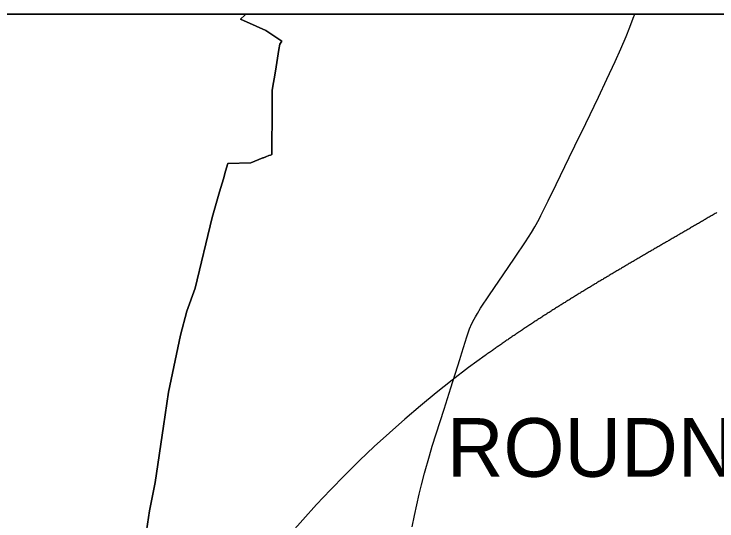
# Model space of a CAD drawing. Extents: x -759276 to -751881, y -1176141 to -1171097.
# Drawn here: x -757130 to -755760, y -1172085 to -1171097 of the extents above; entities that cross this region are included whole.
import ezdxf

# ---------------------------------------------------------------- set-up
doc = ezdxf.new("R2010")
doc.units = 0
for name, color, linetype in [('A_HRU', 7, 'Continuous'), ('A_OBCE', 7, 'Continuous'), ('A_SILNICE', 7, 'Continuous'), ('AA_vyrezy', 7, 'Continuous')]:
    doc.layers.add(name, color=color, linetype=linetype)

msp = doc.modelspace()

# ---------------------------------------------------------------- linework, layer by layer
at = {"layer": 'A_HRU'}
for points in [[(-759275.6, -1176140.6), (-759275.6, -1171097.2), (-751880.9, -1171097.2), (-751880.9, -1176140.6)], [(-751880.9, -1172828.3), (-753894.3, -1172828.3), (-753894.3, -1171097.2), (-759275.6, -1171097.2), (-759275.6, -1176140.6), (-753894.3, -1176140.6), (-753894.3, -1174884.8), (-751880.9, -1174884.8)]]:
    msp.add_lwpolyline(points, close=True, dxfattribs=at)
at = {"layer": 'A_OBCE'}
for p, q in [((-756678.2, -1171097.2), (-757961.8, -1171097.2)), ((-756678.2, -1171097.2), (-756680, -1171099)), ((-755191.2, -1171097.2), (-756678.2, -1171097.2)), ((-756680, -1171099), (-756688.5, -1171107.2)), ((-756657.8, -1171121), (-756688.5, -1171107.2)), ((-756688.5, -1171107.2), (-756657.8, -1171121)), ((-756639.3, -1171129.4), (-756657.8, -1171121)), ((-756657.8, -1171121), (-756639.3, -1171129.4)), ((-756639.3, -1171129.4), (-756607.8, -1171150.2)), ((-756613.8, -1171166.5), (-756619.2, -1171199.9)), ((-756619.2, -1171199.9), (-756622, -1171216.4)), ((-756622, -1171216.4), (-756624.3, -1171230.8)), ((-756624.3, -1171230.8), (-756626.7, -1171245.2)), ((-756626.7, -1171245.2), (-756626.9, -1171278.9)), ((-756633.1, -1171373), (-756630.4, -1171371.9)), ((-756645, -1171377.6), (-756668.7, -1171387)), ((-756643.7, -1171377.1), (-756639.1, -1171375.3)), ((-756639.1, -1171375.3), (-756633.1, -1171373)), ((-756668.7, -1171387), (-756713.4, -1171388.1)), ((-756721.9, -1171418.1), (-756717.7, -1171403.4)), ((-756729.6, -1171443.3), (-756721.9, -1171418.1)), ((-756721.9, -1171418.1), (-756729.6, -1171443.3)), ((-756743.9, -1171493.7), (-756729.6, -1171443.3)), ((-756776.8, -1171631), (-756743.9, -1171493.7)), ((-756828.9, -1171834), (-756805.4, -1171722.9)), ((-756805.4, -1171722.9), (-756828.9, -1171834)), ((-756828.9, -1171834), (-756839, -1171900.1))]:
    msp.add_line(p, q, dxfattribs=at)
for points in [[(-756688.5, -1171107.2), (-756680, -1171099), (-756678.2, -1171097.2)], [(-756613.8, -1171166.5), (-756611.9, -1171155.5), (-756607.8, -1171150.2), (-756639.3, -1171129.4)], [(-756607.8, -1171150.2), (-756611.9, -1171155.5), (-756613.8, -1171166.5)], [(-756626.7, -1171245.2), (-756624.3, -1171230.8), (-756622, -1171216.4), (-756619.2, -1171199.9), (-756613.8, -1171166.5)], [(-756630.4, -1171371.9), (-756627.6, -1171370.8), (-756626.9, -1171278.9), (-756626.7, -1171245.2)], [(-756626.9, -1171278.9), (-756627.6, -1171370.8), (-756630.4, -1171371.9)], [(-756630.4, -1171371.9), (-756633.1, -1171373), (-756639.1, -1171375.3)], [(-756668.7, -1171387), (-756645, -1171377.6), (-756643.7, -1171377.1)], [(-756639.1, -1171375.3), (-756643.7, -1171377.1), (-756645, -1171377.6)], [(-756713.4, -1171388.1), (-756717.7, -1171403.4), (-756721.9, -1171418.1)], [(-756717.7, -1171403.4), (-756713.4, -1171388.1), (-756668.7, -1171387)], [(-756729.6, -1171443.3), (-756743.9, -1171493.7), (-756776.8, -1171631), (-756793.1, -1171676.4), (-756805.4, -1171722.9)], [(-756805.4, -1171722.9), (-756793.1, -1171676.4), (-756776.8, -1171631)], [(-756854.8, -1172009.9), (-756839, -1171900.1), (-756828.9, -1171834)], [(-756839, -1171900.1), (-756854.8, -1172009.9), (-756866.1, -1172065.3)], [(-756881.7, -1172243.8), (-756879.6, -1172156.4), (-756866.1, -1172065.3), (-756854.8, -1172009.9)], [(-756866.1, -1172065.3), (-756879.6, -1172156.4), (-756881.7, -1172243.8)]]:
    msp.add_lwpolyline(points, dxfattribs=at)
at = {"layer": 'A_SILNICE'}
for points in [[(-756353.9, -1172096.2), (-756349.2, -1172074.4), (-756340.1, -1172033), (-756335.9, -1172014.3), (-756330.1, -1171991.7), (-756320.5, -1171958.1), (-756315, -1171939.5), (-756291.9, -1171867.4), (-756278.6, -1171825.2), (-756261.2, -1171770.2), (-756257.2, -1171757.6), (-756247.4, -1171726.4), (-756241.9, -1171710.6), (-756237.4, -1171700.2), (-756233.2, -1171691.6), (-756230.6, -1171686.9), (-756226.9, -1171680.4), (-756220.6, -1171670.2), (-756203.3, -1171644.4), (-756166.8, -1171591.2), (-756153.1, -1171570.9), (-756133.2, -1171540.9), (-756121.6, -1171522.5), (-756114.8, -1171511.6), (-756106.5, -1171496.7), (-756103, -1171490), (-756088.6, -1171461.2), (-756073.1, -1171429.1), (-756047.8, -1171376.9), (-756036.7, -1171354.2), (-756015.5, -1171310.4), (-755990.8, -1171258.9), (-755974.2, -1171223.9), (-755958.4, -1171189.6), (-755947.1, -1171164.8), (-755937.1, -1171141.1), (-755929.7, -1171122.6), (-755923, -1171105.3), (-755920.1, -1171097.2)], [(-755759.8, -1171483.9), (-755761.7, -1171485), (-755763.6, -1171486.1), (-755765.5, -1171487.2), (-755767.4, -1171488.3), (-755769.3, -1171489.4), (-755771.2, -1171490.6), (-755773.1, -1171491.7), (-755775, -1171492.8), (-755776.9, -1171493.9), (-755778.8, -1171495), (-755780.7, -1171496.1), (-755782.6, -1171497.2), (-755784.5, -1171498.3), (-755786.4, -1171499.4), (-755788.3, -1171500.5), (-755790.2, -1171501.6), (-755792.1, -1171502.8), (-755794, -1171503.9), (-755795.9, -1171505), (-755797.8, -1171506.1), (-755799.7, -1171507.2), (-755801.6, -1171508.3), (-755803.5, -1171509.4), (-755805.4, -1171510.5), (-755807.3, -1171511.6), (-755809.2, -1171512.7), (-755811.1, -1171513.8), (-755813, -1171514.9), (-755814.9, -1171516), (-755816.8, -1171517.1), (-755818.7, -1171518.2), (-755820.6, -1171519.4), (-755822.5, -1171520.5), (-755824.4, -1171521.6), (-755826.3, -1171522.7), (-755828.2, -1171523.8), (-755830.1, -1171524.9), (-755832, -1171526), (-755833.9, -1171527.1), (-755835.8, -1171528.2), (-755837.7, -1171529.3), (-755839.6, -1171530.4), (-755841.5, -1171531.5), (-755843.4, -1171532.6), (-755845.3, -1171533.7), (-755847.2, -1171534.8), (-755849.1, -1171535.9), (-755850.9, -1171537), (-755852.8, -1171538.1), (-755854.7, -1171539.1), (-755856.5, -1171540.2), (-755858.4, -1171541.3), (-755860.2, -1171542.4), (-755862.1, -1171543.5), (-755864, -1171544.5), (-755865.8, -1171545.6), (-755867.7, -1171546.7), (-755869.5, -1171547.8), (-755871.4, -1171548.9), (-755873.3, -1171549.9), (-755875.1, -1171551), (-755877, -1171552.1), (-755878.8, -1171553.2), (-755880.7, -1171554.3), (-755882.6, -1171555.3), (-755884.4, -1171556.4), (-755886.3, -1171557.5), (-755888.1, -1171558.6), (-755890, -1171559.7), (-755891.8, -1171560.7), (-755893.7, -1171561.8), (-755895.6, -1171562.9), (-755897.4, -1171564), (-755899.3, -1171565.1), (-755901.1, -1171566.2), (-755903, -1171567.2), (-755904.8, -1171568.3), (-755906.7, -1171569.4), (-755908.6, -1171570.5), (-755910.4, -1171571.6), (-755912.3, -1171572.7), (-755914.1, -1171573.7), (-755916, -1171574.8), (-755917.8, -1171575.9), (-755919.7, -1171577), (-755921.5, -1171578.1), (-755923.4, -1171579.2), (-755925.3, -1171580.3), (-755927.1, -1171581.4), (-755929, -1171582.4), (-755930.8, -1171583.5), (-755932.7, -1171584.6), (-755934.5, -1171585.7), (-755936.4, -1171586.8), (-755938.2, -1171587.9), (-755940.1, -1171589), (-755941.9, -1171590.1), (-755943.8, -1171591.2), (-755945.6, -1171592.3), (-755947.5, -1171593.3), (-755949.3, -1171594.4), (-755951.2, -1171595.5), (-755953, -1171596.6), (-755954.9, -1171597.7), (-755956.7, -1171598.8), (-755958.6, -1171599.9), (-755960.4, -1171601), (-755962.3, -1171602.1), (-755964.1, -1171603.2), (-755966, -1171604.3), (-755967.8, -1171605.4), (-755969.7, -1171606.5), (-755971.5, -1171607.6), (-755973.4, -1171608.7), (-755975.2, -1171609.8), (-755977.1, -1171610.9), (-755978.9, -1171612), (-755980.8, -1171613.1), (-755982.6, -1171614.2), (-755984.5, -1171615.3), (-755986.3, -1171616.4), (-755988.2, -1171617.5), (-755990, -1171618.6), (-755991.8, -1171619.7), (-755993.7, -1171620.8), (-755995.5, -1171621.9), (-755997.4, -1171623.1), (-755999.2, -1171624.2), (-756001, -1171625.3), (-756002.9, -1171626.4), (-756004.7, -1171627.5), (-756006.6, -1171628.6), (-756008.4, -1171629.7), (-756010.2, -1171630.8), (-756012.1, -1171632), (-756013.9, -1171633.1), (-756015.8, -1171634.2), (-756017.6, -1171635.3), (-756019.4, -1171636.4), (-756021.3, -1171637.5), (-756023.1, -1171638.7), (-756024.9, -1171639.8), (-756026.8, -1171640.9), (-756028.6, -1171642), (-756030.4, -1171643.1), (-756032.3, -1171644.3), (-756034.1, -1171645.4), (-756035.9, -1171646.5), (-756037.8, -1171647.6), (-756039.6, -1171648.8), (-756041.4, -1171649.9), (-756043.3, -1171651), (-756045.1, -1171652.2), (-756046.9, -1171653.3), (-756048.7, -1171654.4), (-756050.6, -1171655.6), (-756052.4, -1171656.7), (-756054.2, -1171657.8), (-756056, -1171659), (-756057.9, -1171660.1), (-756059.7, -1171661.2), (-756061.5, -1171662.4), (-756063.3, -1171663.5), (-756065.2, -1171664.7), (-756067, -1171665.8), (-756068.8, -1171667), (-756070.6, -1171668.1), (-756072.4, -1171669.2), (-756074.3, -1171670.4), (-756076.1, -1171671.5), (-756077.9, -1171672.7), (-756079.7, -1171673.8), (-756081.5, -1171675), (-756083.3, -1171676.1), (-756085.2, -1171677.3), (-756087, -1171678.5), (-756088.8, -1171679.6), (-756090.6, -1171680.8), (-756092.4, -1171681.9), (-756094.2, -1171683.1), (-756096, -1171684.2), (-756097.8, -1171685.4), (-756099.6, -1171686.6), (-756101.5, -1171687.7), (-756103.3, -1171688.9), (-756105.1, -1171690.1), (-756106.9, -1171691.2), (-756108.7, -1171692.4), (-756110.5, -1171693.6), (-756112.3, -1171694.7), (-756114.1, -1171695.9), (-756115.9, -1171697.1), (-756117.7, -1171698.3), (-756119.5, -1171699.4), (-756121.3, -1171700.6), (-756123.1, -1171701.8), (-756124.9, -1171703), (-756126.7, -1171704.2), (-756128.5, -1171705.3), (-756130.3, -1171706.5), (-756132.1, -1171707.7), (-756133.9, -1171708.9), (-756135.6, -1171710.1), (-756137.4, -1171711.3), (-756139.2, -1171712.5), (-756141, -1171713.7), (-756142.8, -1171714.9), (-756144.6, -1171716.1), (-756146.4, -1171717.3), (-756148.2, -1171718.5), (-756149.9, -1171719.7), (-756151.7, -1171720.9), (-756153.5, -1171722.1), (-756155.3, -1171723.3), (-756157.1, -1171724.5), (-756158.8, -1171725.7), (-756160.6, -1171726.9), (-756162.4, -1171728.1), (-756164.2, -1171729.3), (-756166, -1171730.5), (-756167.7, -1171731.7), (-756169.5, -1171732.9), (-756171.3, -1171734.2), (-756173, -1171735.4), (-756174.8, -1171736.6), (-756176.6, -1171737.8), (-756178.3, -1171739.1), (-756180.1, -1171740.3), (-756181.9, -1171741.5), (-756183.6, -1171742.7), (-756185.4, -1171744), (-756187.2, -1171745.2), (-756188.9, -1171746.4), (-756190.7, -1171747.7), (-756192.4, -1171748.9), (-756194.2, -1171750.1), (-756196, -1171751.4), (-756197.7, -1171752.6), (-756199.5, -1171753.9), (-756201.2, -1171755.1), (-756203, -1171756.4), (-756204.7, -1171757.6), (-756206.5, -1171758.9), (-756208.2, -1171760.1), (-756210, -1171761.4), (-756211.7, -1171762.6), (-756243.9, -1171786.2), (-756275.7, -1171810.4), (-756307.1, -1171835.2), (-756337.9, -1171860.6), (-756368.4, -1171886.5), (-756398.3, -1171912.9), (-756427.8, -1171939.9), (-756456.7, -1171967.4), (-756485.2, -1171995.5), (-756513.1, -1172024), (-756540.5, -1172053.1), (-756567.4, -1172082.7), (-756593.8, -1172112.7)]]:
    msp.add_lwpolyline(points, dxfattribs=at)

# ---------------------------------------------------------------- texts
at = {"layer": 'AA_vyrezy'}
msp.add_text('ROUDNÉ', height=114.37, rotation=360, dxfattribs=at).set_placement((-756286.5, -1171998.9))

doc.saveas('drawing.dxf')
